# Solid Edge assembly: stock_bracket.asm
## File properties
Author: Deepak Maini
Template: Normal.asm
Last saved by: MYPC
Revision: 25
Application: Solid Edge
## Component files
Stock_support_base.par
thrust_bearing.par
adjusting_screw_nut.par
support_adjusting_screw.par
support_roller_bracket.par
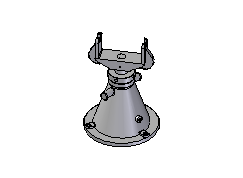
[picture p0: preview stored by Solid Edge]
